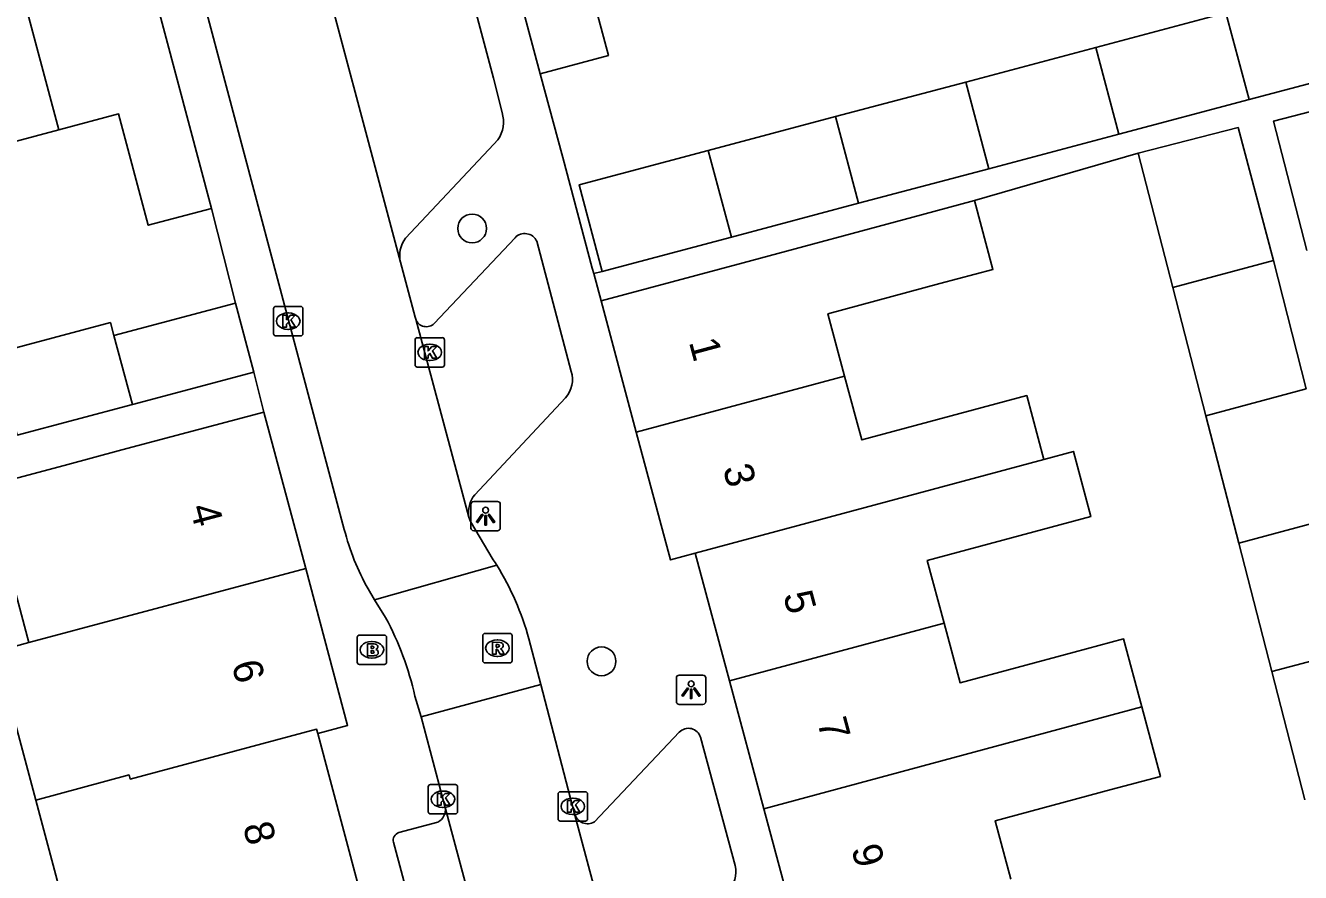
# Model space of a CAD drawing. Extents: x 162542 to 163144, y 380786 to 381511.
# Drawn here: x 162798.21 to 162841.58, y 381024.22 to 381053.03 of the extents above; entities that cross this region are included whole.
import ezdxf

# ---------------------------------------------------------------- set-up
doc = ezdxf.new("R2010")
doc.units = 0
for name, color, linetype in [('IMGEO_Boom', 7, 'Continuous'), ('IMGEO_Brandkraan', 7, 'Continuous'), ('IMGEO_Kolk', 7, 'Continuous'), ('IMGEO_Lichtpunt', 7, 'Continuous'), ('IMGEO_Muur', 7, 'Continuous'), ('IMGEO_Pand', 7, 'Continuous'), ('IMGEO_Pand_nummerreeks', 7, 'Continuous'), ('IMGEO_Rijbaan_lokaal_open', 7, 'Continuous'), ('IMGEO_Rioolput', 7, 'Continuous'), ('IMGEO_Voetpad_open', 7, 'Continuous')]:
    doc.layers.add(name, color=color, linetype=linetype)

msp = doc.modelspace()

# ---------------------------------------------------------------- linework, layer by layer
at = {"layer": 'IMGEO_Boom'}
for centre in [(162813.401, 381046.126), (162817.803, 381031.404)]:
    msp.add_circle(centre, 0.489, dxfattribs=at)
at = {"layer": 'IMGEO_Brandkraan'}
for p, q in [((162809.567, 381032.295), (162810.419, 381032.295)), ((162809.492, 381031.369), (162809.492, 381032.221)), ((162809.98, 381032.075), (162810.005, 381032.075)), ((162810.493, 381032.221), (162810.493, 381031.369)), ((162810.003, 381031.515), (162809.978, 381031.515)), ((162810.419, 381031.295), (162809.567, 381031.295))]:
    msp.add_line(p, q, dxfattribs=at)
for points in [[(162809.567, 381032.295), (162810.419, 381032.295)], [(162809.492, 381031.369), (162809.492, 381032.221)], [(162809.84, 381031.995), (162809.84, 381031.595), (162810.053, 381031.595)], [(162810.071, 381031.995), (162809.84, 381031.995)], [(162810.019, 381031.914), (162809.965, 381031.914), (162809.965, 381031.838)], [(162809.965, 381031.838), (162810.018, 381031.838)], [(162810.493, 381032.221), (162810.493, 381031.369)], [(162810.027, 381031.762), (162809.965, 381031.762), (162809.965, 381031.681)], [(162809.965, 381031.681), (162810.027, 381031.681)], [(162810.419, 381031.295), (162809.567, 381031.295)]]:
    msp.add_lwpolyline(points, dxfattribs=at)
for centre, radius, start, end in [((162809.569, 381032.219), 0.0765, 91.552, 178.448), ((162809.569, 381032.219), 0.0765, 91.552, 178.448), ((162810.417, 381032.219), 0.0765, 1.552, 88.448), ((162810.417, 381032.219), 0.0765, 1.552, 88.448), ((162810.02, 381031.876), 0.0379, 267.8285, 90.9355), ((162810.075, 381031.85), 0.145, 59.4692, 91.5367), ((162810.1, 381031.897), 0.0922, 285.5137, 58.1501), ((162810.105, 381031.705), 0.105, 301.3115, 78.989), ((162810.028, 381031.721), 0.0404, 269.8759, 90.5077), ((162810.059, 381031.846), 0.251, 268.6676, 293.5347), ((162809.569, 381031.371), 0.0765, 181.552, 268.448), ((162809.569, 381031.371), 0.0765, 181.552, 268.448), ((162810.417, 381031.371), 0.0765, 271.552, 358.448), ((162810.417, 381031.371), 0.0765, 271.552, 358.448)]:
    msp.add_arc(centre, radius, start, end, dxfattribs=at)
for centre, major_axis, ratio, start_param, end_param in [((162809.979, 381031.795), (-0.387, 0.002), 0.722429, 4.712389, 7.853982), ((162810.004, 381031.795), (-0.39, 0.002), 0.717154, 1.570796, 4.712389)]:
    msp.add_ellipse(centre, major_axis=major_axis, ratio=ratio, start_param=start_param, end_param=end_param, dxfattribs=at)
at = {"layer": 'IMGEO_Kolk'}
for p, q in [((162806.644, 381042.548), (162806.644, 381043.4)), ((162806.719, 381043.474), (162807.571, 381043.474)), ((162807.132, 381043.254), (162807.157, 381043.254)), ((162807.645, 381043.4), (162807.645, 381042.548)), ((162807.155, 381042.694), (162807.13, 381042.694)), ((162807.571, 381042.474), (162806.719, 381042.474)), ((162811.46, 381041.486), (162811.46, 381042.338)), ((162811.535, 381042.412), (162812.387, 381042.412)), ((162812.461, 381042.338), (162812.461, 381041.486)), ((162811.948, 381042.192), (162811.973, 381042.192)), ((162812.387, 381041.412), (162811.535, 381041.412)), ((162811.971, 381041.632), (162811.946, 381041.632)), ((162811.907, 381026.286), (162811.907, 381027.138)), ((162811.982, 381027.212), (162812.834, 381027.212)), ((162812.908, 381027.138), (162812.908, 381026.286)), ((162812.395, 381026.992), (162812.42, 381026.992)), ((162816.326, 381026.042), (162816.326, 381026.894)), ((162816.401, 381026.968), (162817.253, 381026.968)), ((162816.814, 381026.748), (162816.839, 381026.748)), ((162817.327, 381026.894), (162817.327, 381026.042)), ((162812.834, 381026.212), (162811.982, 381026.212)), ((162812.418, 381026.432), (162812.393, 381026.432)), ((162816.837, 381026.188), (162816.812, 381026.188)), ((162817.253, 381025.968), (162816.401, 381025.968))]:
    msp.add_line(p, q, dxfattribs=at)
for points in [[(162806.644, 381042.548), (162806.644, 381043.4)], [(162806.719, 381043.474), (162807.571, 381043.474)], [(162806.965, 381043.174), (162807.088, 381043.174), (162807.088, 381043.023), (162807.218, 381043.174), (162807.382, 381043.174), (162807.236, 381043.023), (162807.389, 381042.774), (162807.237, 381042.774), (162807.152, 381042.938), (162807.088, 381042.871), (162807.088, 381042.774), (162806.965, 381042.774), (162806.965, 381043.174)], [(162807.645, 381043.4), (162807.645, 381042.548)], [(162807.571, 381042.474), (162806.719, 381042.474)], [(162811.46, 381041.486), (162811.46, 381042.338)], [(162811.535, 381042.412), (162812.387, 381042.412)], [(162812.461, 381042.338), (162812.461, 381041.486)], [(162811.781, 381042.112), (162811.904, 381042.112), (162811.904, 381041.961), (162812.034, 381042.112), (162812.198, 381042.112), (162812.052, 381041.961), (162812.205, 381041.712), (162812.053, 381041.712), (162811.968, 381041.876), (162811.904, 381041.809), (162811.904, 381041.712), (162811.781, 381041.712), (162811.781, 381042.112)], [(162812.387, 381041.412), (162811.535, 381041.412)], [(162811.907, 381026.286), (162811.907, 381027.138)], [(162811.982, 381027.212), (162812.834, 381027.212)], [(162812.908, 381027.138), (162812.908, 381026.286)], [(162812.228, 381026.912), (162812.351, 381026.912), (162812.351, 381026.761), (162812.481, 381026.912), (162812.645, 381026.912), (162812.499, 381026.761), (162812.652, 381026.512), (162812.5, 381026.512), (162812.415, 381026.676), (162812.351, 381026.609), (162812.351, 381026.512), (162812.228, 381026.512), (162812.228, 381026.912)], [(162816.326, 381026.042), (162816.326, 381026.894)], [(162816.401, 381026.968), (162817.253, 381026.968)], [(162816.647, 381026.668), (162816.77, 381026.668), (162816.77, 381026.517), (162816.9, 381026.668), (162817.064, 381026.668), (162816.918, 381026.517), (162817.071, 381026.268), (162816.919, 381026.268), (162816.834, 381026.432), (162816.77, 381026.365), (162816.77, 381026.268), (162816.647, 381026.268), (162816.647, 381026.668)], [(162817.327, 381026.894), (162817.327, 381026.042)], [(162812.834, 381026.212), (162811.982, 381026.212)], [(162817.253, 381025.968), (162816.401, 381025.968)]]:
    msp.add_lwpolyline(points, dxfattribs=at)
for centre, start, end in [((162806.721, 381043.398), 91.552, 178.448), ((162806.721, 381043.398), 91.552, 178.448), ((162807.569, 381043.398), 1.552, 88.448), ((162807.569, 381043.398), 1.552, 88.448), ((162806.721, 381042.55), 181.552, 268.448), ((162806.721, 381042.55), 181.552, 268.448), ((162807.569, 381042.55), 271.552, 358.448), ((162807.569, 381042.55), 271.552, 358.448), ((162811.537, 381042.336), 91.552, 178.448), ((162811.537, 381042.336), 91.552, 178.448), ((162812.385, 381042.336), 1.552, 88.448), ((162812.385, 381042.336), 1.552, 88.448), ((162811.537, 381041.488), 181.552, 268.448), ((162811.537, 381041.488), 181.552, 268.448), ((162812.385, 381041.488), 271.552, 358.448), ((162812.385, 381041.488), 271.552, 358.448), ((162811.984, 381027.136), 91.552, 178.448), ((162811.984, 381027.136), 91.552, 178.448), ((162812.832, 381027.136), 1.552, 88.448), ((162812.832, 381027.136), 1.552, 88.448), ((162816.403, 381026.892), 91.552, 178.448), ((162816.403, 381026.892), 91.552, 178.448), ((162817.251, 381026.892), 1.552, 88.448), ((162817.251, 381026.892), 1.552, 88.448), ((162811.984, 381026.288), 181.552, 268.448), ((162811.984, 381026.288), 181.552, 268.448), ((162812.832, 381026.288), 271.552, 358.448), ((162812.832, 381026.288), 271.552, 358.448), ((162816.403, 381026.044), 181.552, 268.448), ((162816.403, 381026.044), 181.552, 268.448), ((162817.251, 381026.044), 271.552, 358.448), ((162817.251, 381026.044), 271.552, 358.448)]:
    msp.add_arc(centre, 0.0765, start, end, dxfattribs=at)
for centre, major_axis, ratio, start_param, end_param in [((162807.131, 381042.974), (-0.387, 0.002), 0.722429, 4.712389, 7.853982), ((162807.156, 381042.974), (-0.39, 0.002), 0.717154, 1.570796, 4.712389), ((162811.947, 381041.912), (-0.387, 0.002), 0.722429, 4.712389, 7.853982), ((162811.972, 381041.912), (-0.39, 0.002), 0.717154, 1.570796, 4.712389), ((162812.394, 381026.712), (-0.387, 0.002), 0.722429, 4.712389, 7.853982), ((162812.419, 381026.712), (-0.39, 0.002), 0.717154, 1.570796, 4.712389), ((162816.813, 381026.468), (-0.387, 0.002), 0.722429, 4.712389, 7.853982), ((162816.838, 381026.468), (-0.39, 0.002), 0.717154, 1.570796, 4.712389)]:
    msp.add_ellipse(centre, major_axis=major_axis, ratio=ratio, start_param=start_param, end_param=end_param, dxfattribs=at)
at = {"layer": 'IMGEO_Lichtpunt'}
for p, q in [((162813.362, 381036.745), (162813.362, 381035.938)), ((162813.362, 381036.745), (162813.362, 381035.938)), ((162814.264, 381036.84), (162813.456, 381036.84)), ((162814.264, 381036.84), (162813.456, 381036.84)), ((162814.358, 381035.938), (162814.358, 381036.745)), ((162814.358, 381035.938), (162814.358, 381036.745)), ((162813.456, 381035.844), (162814.264, 381035.844)), ((162813.456, 381035.844), (162814.264, 381035.844)), ((162820.351, 381030.839), (162820.351, 381030.032)), ((162820.351, 381030.839), (162820.351, 381030.032)), ((162821.253, 381030.934), (162820.445, 381030.934)), ((162821.253, 381030.934), (162820.445, 381030.934)), ((162821.347, 381030.032), (162821.347, 381030.839)), ((162821.347, 381030.032), (162821.347, 381030.839)), ((162820.445, 381029.938), (162821.253, 381029.938)), ((162820.445, 381029.938), (162821.253, 381029.938))]:
    msp.add_line(p, q, dxfattribs=at)
for points in [[(162813.736, 381036.409), (162813.775, 381036.381), (162813.587, 381036.119), (162813.549, 381036.146), (162813.736, 381036.409)], [(162813.838, 381036.361), (162813.885, 381036.361), (162813.885, 381036.039), (162813.838, 381036.039), (162813.838, 381036.361)], [(162813.948, 381036.381), (162813.986, 381036.408), (162814.173, 381036.146), (162814.134, 381036.118), (162813.948, 381036.381)], [(162820.725, 381030.503), (162820.764, 381030.475), (162820.576, 381030.213), (162820.538, 381030.24), (162820.725, 381030.503)], [(162820.827, 381030.455), (162820.874, 381030.455), (162820.874, 381030.133), (162820.827, 381030.133), (162820.827, 381030.455)], [(162820.937, 381030.475), (162820.975, 381030.502), (162821.162, 381030.24), (162821.123, 381030.212), (162820.937, 381030.475)]]:
    msp.add_lwpolyline(points, dxfattribs=at)
for centre in [(162813.861, 381036.543), (162820.85, 381030.637)]:
    msp.add_circle(centre, 0.0994, dxfattribs=at)
for centre, start, end in [((162813.456, 381036.745), 90, 180), ((162813.456, 381036.745), 90, 180), ((162814.264, 381036.745), 0, 90), ((162814.264, 381036.745), 0, 90), ((162813.456, 381035.938), 180, 270), ((162813.456, 381035.938), 180, 270), ((162814.264, 381035.938), 270, 0), ((162814.264, 381035.938), 270, 360), ((162820.445, 381030.839), 90, 180), ((162820.445, 381030.839), 90, 180), ((162821.253, 381030.839), 0, 90), ((162821.253, 381030.839), 0, 90), ((162820.445, 381030.032), 180, 270), ((162820.445, 381030.032), 180, 270), ((162821.253, 381030.032), 270, 0), ((162821.253, 381030.032), 270, 360)]:
    msp.add_arc(centre, 0.0946, start, end, dxfattribs=at)
at = {"layer": 'IMGEO_Muur'}
for points in [[(162815.721, 381051.384), (162816.482, 381048.541)], [(162804.535, 381046.81), (162805.355, 381043.584)]]:
    msp.add_lwpolyline(points, dxfattribs=at)
at = {"layer": 'IMGEO_Pand'}
for points in [[(162815.721, 381051.384), (162812.82, 381062.202)], [(162801.405, 381058.58), (162804.535, 381046.81)], [(162799.344, 381049.481), (162797.213, 381057.434)], [(162819.336, 381056.495), (162817.004, 381055.87), (162818.039, 381052.006), (162815.721, 381051.384)], [(162839.045, 381053.458), (162834.619, 381052.282)], [(162839.83, 381050.509), (162839.045, 381053.458)], [(162834.619, 381052.282), (162830.194, 381051.107)], [(162834.619, 381052.282), (162835.403, 381049.334)], [(162839.83, 381050.509), (162844.255, 381051.684)], [(162825.76, 381049.93), (162830.194, 381051.107)], [(162830.194, 381051.107), (162830.978, 381048.159)], [(162835.403, 381049.334), (162839.83, 381050.509)], [(162843.91, 381050.614), (162840.667, 381049.779), (162841.791, 381045.377)], [(162804.535, 381046.81), (162802.384, 381046.237), (162801.377, 381050.022), (162799.344, 381049.481)], [(162821.428, 381048.78), (162825.76, 381049.93)], [(162825.76, 381049.93), (162826.546, 381046.982)], [(162799.344, 381049.481), (162794.163, 381048.103)], [(162830.978, 381048.159), (162835.403, 381049.334)], [(162840.659, 381045.033), (162839.456, 381049.56), (162836.064, 381048.686)], [(162817.82, 381044.665), (162817.037, 381047.614), (162821.428, 381048.78)], [(162822.226, 381045.835), (162821.428, 381048.78)], [(162836.064, 381048.686), (162837.242, 381044.114)], [(162826.546, 381046.982), (162830.978, 381048.159)], [(162830.489, 381047.074), (162828.685, 381046.589), (162822.616, 381044.959), (162817.787, 381043.662)], [(162826.074, 381041.108), (162825.505, 381043.228), (162829.313, 381044.251), (162831.117, 381044.736), (162830.489, 381047.074)], [(162822.226, 381045.835), (162826.546, 381046.982)], [(162817.82, 381044.665), (162822.226, 381045.835)], [(162837.242, 381044.114), (162840.659, 381045.033)], [(162841.769, 381040.673), (162840.659, 381045.033)], [(162837.242, 381044.114), (162838.364, 381039.756)], [(162801.215, 381042.483), (162805.355, 381043.584)], [(162805.355, 381043.584), (162805.979, 381041.236)], [(162818.985, 381039.2), (162817.787, 381043.662)], [(162797.923, 381039.094), (162797.182, 381041.883), (162801.098, 381042.925), (162801.215, 381042.483)], [(162801.848, 381040.138), (162801.215, 381042.483)], [(162805.979, 381041.236), (162801.848, 381040.138)], [(162818.985, 381039.2), (162826.074, 381041.108)], [(162832.853, 381038.273), (162832.27, 381040.442), (162826.657, 381038.935), (162826.467, 381039.643), (162826.074, 381041.108)], [(162841.769, 381040.673), (162838.364, 381039.756)], [(162801.848, 381040.138), (162797.923, 381039.094)], [(162794.663, 381036.768), (162799.525, 381038.068), (162801.485, 381038.592), (162806.315, 381039.883)], [(162806.315, 381039.883), (162807.74, 381034.555)], [(162838.364, 381039.756), (162839.48, 381035.426)], [(162820.985, 381035.078), (162820.152, 381034.854), (162818.985, 381039.2)], [(162829.455, 381032.699), (162828.882, 381034.83), (162832.803, 381035.883), (162834.452, 381036.326), (162833.857, 381038.543), (162832.853, 381038.273)], [(162832.853, 381038.273), (162820.985, 381035.078)], [(162798.325, 381032.038), (162797.365, 381035.632), (162795.127, 381035.034), (162794.663, 381036.768)], [(162842.898, 381036.336), (162839.48, 381035.426)], [(162839.48, 381035.426), (162840.606, 381031.053)], [(162822.153, 381030.734), (162820.985, 381035.078)], [(162807.74, 381034.555), (162798.325, 381032.038)], [(162807.74, 381034.555), (162809.165, 381029.223), (162808.147, 381028.951)], [(162829.455, 381032.699), (162822.153, 381030.734)], [(162836.183, 381029.85), (162835.564, 381032.168), (162833.885, 381031.717), (162829.999, 381030.674), (162829.455, 381032.699)], [(162798.554, 381026.681), (162797.202, 381031.738), (162798.325, 381032.038)], [(162840.606, 381031.053), (162844.036, 381031.966)], [(162840.606, 381031.053), (162841.729, 381026.695)], [(162823.321, 381026.389), (162822.153, 381030.734)], [(162823.321, 381026.389), (162836.183, 381029.85)], [(162836.183, 381029.85), (162836.814, 381027.489), (162835.142, 381027.04), (162831.192, 381025.979), (162831.725, 381023.992)], [(162798.554, 381026.681), (162801.73, 381027.542), (162801.769, 381027.398), (162808.109, 381029.095), (162808.147, 381028.951)], [(162808.147, 381028.951), (162809.505, 381023.876)], [(162799.976, 381021.363), (162798.554, 381026.681)], [(162824.489, 381022.045), (162823.321, 381026.389)]]:
    msp.add_lwpolyline(points, dxfattribs=at)
at = {"layer": 'IMGEO_Rijbaan_lokaal_open'}
for points in [[(162807.705, 381057.197), (162810.965, 381044.975)], [(162809.054, 381035.885), (162803.658, 381056.146)], [(162810.965, 381044.975), (162811.46, 381043.114), (162811.481, 381043.036)], [(162811.481, 381043.036), (162813.294, 381036.307)], [(162813.294, 381036.307), (162813.347, 381036.159), (162814.12, 381034.858), (162814.18, 381034.764), (162814.24, 381034.67)], [(162814.24, 381034.67), (162810.075, 381033.491)], [(162810.075, 381033.491), (162809.86, 381033.864)], [(162810.458, 381032.89), (162810.075, 381033.491)], [(162815.332, 381032.168), (162815.739, 381030.611)], [(162815.739, 381030.611), (162811.664, 381029.519)], [(162815.739, 381030.611), (162816.885, 381026.221)], [(162811.664, 381029.519), (162811.457, 381030.217)], [(162812.488, 381026.429), (162811.664, 381029.519)], [(162812.488, 381026.429), (162820.436, 380996.76)], [(162824.931, 380996.132), (162816.885, 381026.221)]]:
    msp.add_lwpolyline(points, dxfattribs=at)
for centre, radius, start, end in [((162817.524, 381038.092), 8.753, 194.6029, 208.8826), ((162806.119, 381029.636), 9.554, 15.3653, 31.7925), ((162800.963, 381027.818), 10.765, 12.8762, 28.109)]:
    msp.add_arc(centre, radius, start, end, dxfattribs=at)
at = {"layer": 'IMGEO_Rioolput'}
for p, q in [((162813.761, 381031.425), (162813.761, 381032.277)), ((162813.836, 381032.351), (162814.688, 381032.351)), ((162814.762, 381032.277), (162814.762, 381031.425)), ((162814.249, 381032.131), (162814.274, 381032.131)), ((162814.272, 381031.571), (162814.247, 381031.571)), ((162814.688, 381031.351), (162813.836, 381031.351))]:
    msp.add_line(p, q, dxfattribs=at)
for points in [[(162813.761, 381031.425), (162813.761, 381032.277)], [(162813.836, 381032.351), (162814.688, 381032.351)], [(162814.762, 381032.277), (162814.762, 381031.425)], [(162814.35, 381032.049), (162814.098, 381032.051), (162814.098, 381031.651)], [(162814.098, 381031.651), (162814.222, 381031.651), (162814.222, 381031.813), (162814.233, 381031.813)], [(162814.276, 381031.97), (162814.222, 381031.97), (162814.222, 381031.889)], [(162814.222, 381031.889), (162814.274, 381031.889)], [(162814.28, 381031.784), (162814.351, 381031.651), (162814.491, 381031.651), (162814.426, 381031.777)], [(162814.688, 381031.351), (162813.836, 381031.351)]]:
    msp.add_lwpolyline(points, dxfattribs=at)
for centre, radius, start, end in [((162813.838, 381032.275), 0.0765, 91.552, 178.448), ((162813.838, 381032.275), 0.0765, 91.552, 178.448), ((162814.686, 381032.275), 0.0765, 1.552, 88.448), ((162814.686, 381032.275), 0.0765, 1.552, 88.448), ((162814.232, 381031.76), 0.0533, 26.0293, 88.6989), ((162814.258, 381032.078), 0.19, 274.7715, 282.9687), ((162814.282, 381031.874), 0.0964, 77.0061, 93.1865), ((162814.296, 381031.931), 0.0378, 276.6634, 79.6772), ((162814.349, 381031.939), 0.109, 350.3612, 89.416), ((162814.347, 381031.939), 0.112, 277.5842, 350.9817), ((162814.331, 381031.724), 0.108, 29.5134, 73.7905), ((162813.838, 381031.427), 0.0765, 181.552, 268.448), ((162813.838, 381031.427), 0.0765, 181.552, 268.448), ((162814.686, 381031.427), 0.0765, 271.552, 358.448), ((162814.686, 381031.427), 0.0765, 271.552, 358.448)]:
    msp.add_arc(centre, radius, start, end, dxfattribs=at)
for centre, major_axis, ratio, start_param, end_param in [((162814.248, 381031.851), (-0.387, 0.002), 0.722429, 4.712389, 7.853982), ((162814.273, 381031.851), (-0.39, 0.002), 0.717154, 1.570796, 4.712389)]:
    msp.add_ellipse(centre, major_axis=major_axis, ratio=ratio, start_param=start_param, end_param=end_param, dxfattribs=at)
at = {"layer": 'IMGEO_Voetpad_open'}
for points in [[(162811.8, 381059.973), (162814.132, 381051.236), (162814.418, 381050.071)], [(162817.539, 381044.59), (162817.49, 381044.774), (162816.482, 381048.541), (162815.721, 381051.384)], [(162814.276, 381049.142), (162814.143, 381048.99), (162811.135, 381045.792)], [(162836.064, 381048.686), (162830.489, 381047.074)], [(162805.355, 381043.584), (162804.535, 381046.81)], [(162812.114, 381042.894), (162814.861, 381045.812)], [(162815.601, 381045.695), (162816.772, 381041.265)], [(162817.539, 381044.59), (162817.82, 381044.665)], [(162817.787, 381043.662), (162817.539, 381044.59)], [(162806.315, 381039.883), (162805.979, 381041.236)], [(162816.579, 381040.371), (162813.491, 381037.066)], [(162817.566, 381025.939), (162820.45, 381028.994)], [(162821.171, 381028.818), (162822.349, 381024.455)], [(162810.906, 381025.578), (162812.24, 381025.935)], [(162818.311, 380996.879), (162810.726, 381025.248)]]:
    msp.add_lwpolyline(points, dxfattribs=at)
for centre, radius, start, end in [((162813.431, 381049.746), 1.039, 324.4114, 18.2076), ((162811.902, 381045.206), 0.965, 142.6399, 193.8515), ((162815.191, 381045.5), 0.454, 25.4414, 136.5895), ((162811.845, 381043.176), 0.39, 201.0252, 313.6872), ((162815.882, 381040.989), 0.932, 318.4253, 17.2102), ((162814.204, 381036.476), 0.926, 140.3997, 190.5), ((162820.759, 381028.696), 0.429, 16.5026, 136.0615), ((162812, 381026.365), 0.492, 299.1802, 7.5043), ((162817.335, 381026.345), 0.467, 195.4374, 299.574), ((162810.989, 381025.319), 0.272, 107.7163, 195.0628), ((162821.481, 381024.238), 0.895, 312.5512, 14.0264)]:
    msp.add_arc(centre, radius, start, end, dxfattribs=at)

# ---------------------------------------------------------------- texts
at = {"layer": 'IMGEO_Pand_nummerreeks'}
for s, rotation, p in [('1', 285.0298, (162820.77, 381042.269)), ('3', 285.0285, (162821.924, 381037.975)), ('4', 284.9682, (162803.787, 381036.637)), ('5', 285.0514, (162823.975, 381033.662)), ('6', 284.9682, (162805.212, 381031.307)), ('7', 285.0507, (162825.134, 381029.349)), ('8', 284.9845, (162805.594, 381025.802)), ('9', 285.0507, (162826.294, 381025.037))]:
    msp.add_text(s, height=1, rotation=rotation, dxfattribs=at).set_placement(p)

doc.saveas('drawing.dxf')
